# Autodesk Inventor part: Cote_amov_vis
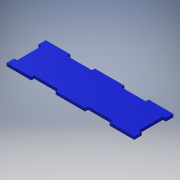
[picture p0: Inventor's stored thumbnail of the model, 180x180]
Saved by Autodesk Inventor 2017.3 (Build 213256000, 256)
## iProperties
Part Number: Cote_amov_vis
Material: Générique
Document SubType Name: Modeling
Designer: ficho
Density: 1 g/cm^3
Appearance: Bleu - Peinture murale - Brillant
Author: ficho
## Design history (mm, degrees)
sketch "Esquisse1"
  geometry: L1 (80.15, -37)-(80.15, -34); L2 (80.15, -34)-(55.15, -34); L3 (55.15, -34)-(55.15, -37); L4 (80.15, 0)-(55.15, 0); L5 (55.15, 0)-(55.15, 3); L6 (80.15, 3)-(80.15, 0); L7 (0.15, 0)-(25.15, 0); L8 (25.15, 0)-(25.15, 3); L9 (0.15, -37)-(0.15, -34); L10 (0.15, -34)-(25.15, -34); L11 (25.15, -34)-(25.15, -37); L12 (-25, -4.65)-(-22, -4.65); L13 (-22, -4.65)-(-22, -29.35); L14 (-22, -29.35)-(-25, -29.35); L15 (105.3, -4.65)-(102.3, -4.65); L16 (102.3, -4.65)-(102.3, -29.35); L17 (102.3, -29.35)-(105.3, -29.35); L18 (105.3, -37)-(105.3, -29.35); L19 (105.3, -4.65)-(105.3, 3); L20 (80.3, 0)-(80.3, 3) reference; L21 (55, 0)-(55, 3) reference; L22 (80.3, -37)-(80.3, -34) reference; L23 (55, -37)-(55, -34) reference; L24 (25.3, -37)-(25.3, -34) reference; L25 (25.3, 0)-(25.3, 3) reference; L26 (0, 0)-(0, 3) reference; L27 (0, -37)-(0, -34) reference; L28 (80.15, -37)-(105.3, -37); L29 (105.3, 3)-(80.15, 3); L30 (-25, -37)-(0.15, -37); L31 (25.15, -37)-(55.15, -37); L32 (-25, -29.35)-(-25, -37); L33 (55.15, 3)-(25.15, 3); L34 (-25, -4.65)-(-25, 3); L35 (-25, 3)-(0.15, 3); L36 (0.15, 0)-(0.15, 3); 1 further point
  constraints: 56 end point, 10 parallel, 6 perpendicular, 5 horizontal, 2 point on line, 1 vertical, 4 other
  dimensions: "d0" = 3 distance of L1.end L1.start; "d1" = 3 distance of L13.end L14.end; "d2" = 24.7 distance of L12.end L13.end; "d3" = 3 distance of L17.end L16.end; "d4" = 24.7 distance of L16.end L15.end; "d7" = 3 distance between parallel lines of L19 L16; "d8" = 0.15 distance between parallel lines of L25 L8; "d10" = 0.15 distance between parallel lines of L27 L9 (= d9); "d11" = 0.15 distance between parallel lines of L11 L24 (= d8); "d12" = 0.15 distance between parallel lines of L5 L21 (= d8); "d13" = 0.15 distance between parallel lines of L6 L20 (= d12); "d14" = 0.15 distance between parallel lines of L22 L1 (= d13); "d15" = 0.15 distance between parallel lines of L3 L23 (= d12); "d19" = 7.65 distance between parallel lines of L30 L14; "d20" = 7.65 distance between parallel lines of L35 L12 (derived)
  node "Référence1"
  node "Référence2"
  node "Référence3"
  node "Référence4"
  node "Référence5"
  node "Référence6"
  node "Référence7"
  node "Référence8"
node "Plan de construction1"
extrude "Extrusion1" new body sketch "Esquisse1" stored distance "d16" = 10; taper "d17" = 0 deg
node "Solide1"
other parameters: "d5" = 7.65, "d6" = 7.65 (derived), "d9" = 0.15 (= d8)
